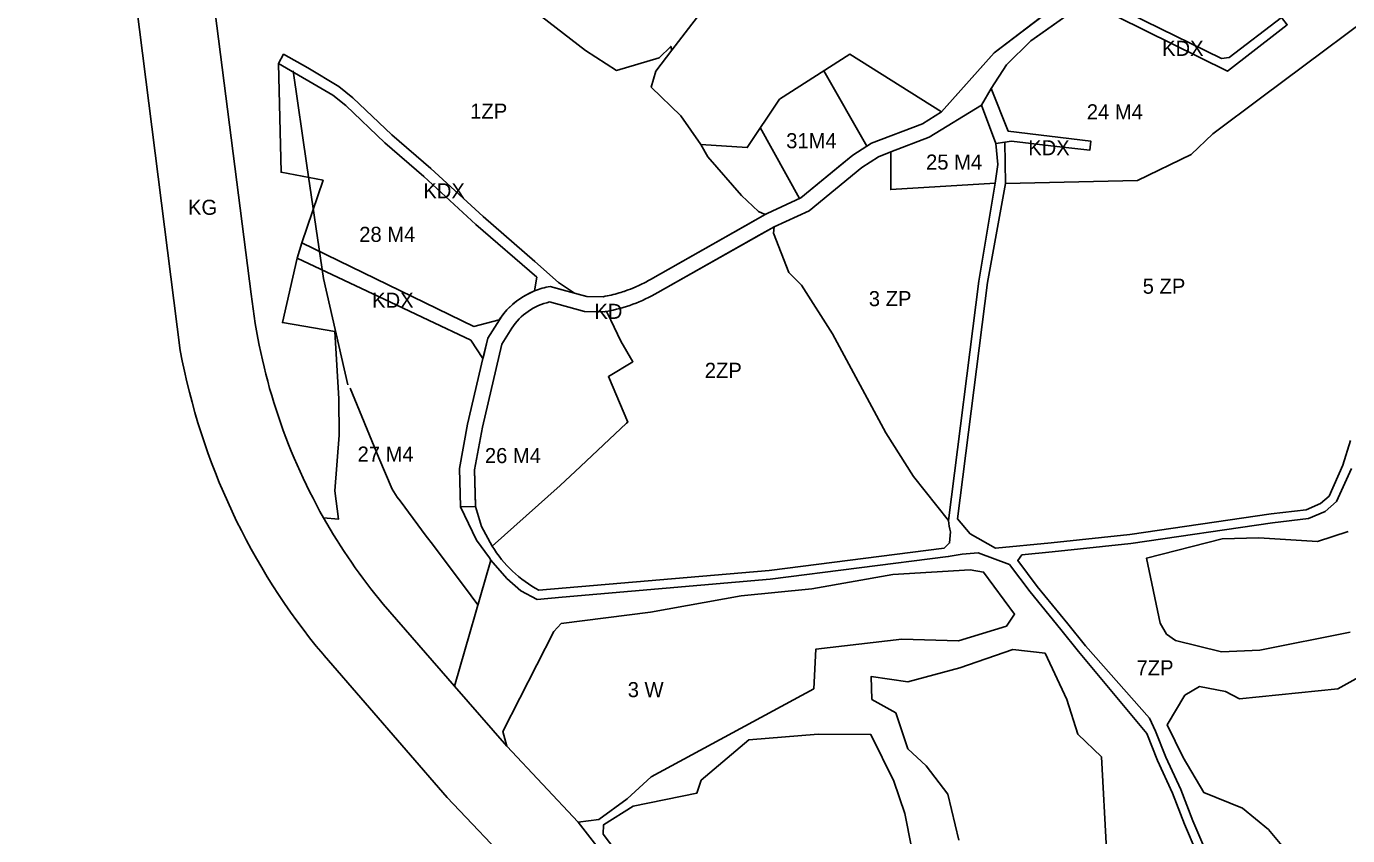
# Model space of a CAD drawing. Extents: x 7437831 to 7440315, y 5545798 to 5547888.
# Drawn here: x 7437831 to 7438706, y 5546452 to 5546989 of the extents above; entities that cross this region are included whole.
import ezdxf

# ---------------------------------------------------------------- set-up
doc = ezdxf.new("R2010")
doc.units = 0
for name, color, linetype in [('linie_rozgraniczajace', 7, 'Continuous'), ('linie_zabudowy_nieprzekraczalne', 7, 'Continuous'), ('oznaczenia_przeznaczen', 7, 'Continuous')]:
    doc.layers.add(name, color=color, linetype=linetype)

msp = doc.modelspace()

# ---------------------------------------------------------------- linework, layer by layer
at = {"layer": 'linie_rozgraniczajace'}
for points in [[(7437933.01, 5546774.06), (7437837.44, 5547527.72), (7437831.07, 5547588.73), (7437881.01, 5547594.89)], [(7437914.41, 5547332.12), (7437921.2, 5547271.7), (7437934.23, 5547169.76), (7437938.07, 5547139.68), (7437980.02, 5546811.4)], [(7437934.23, 5547169.76), (7437970.63, 5547155.76), (7437998.58, 5547150.47), (7438047.18, 5547119.28), (7438140.24, 5547033.26), (7438172.32, 5546995.35), (7438201.42, 5546972.84), (7438222.04, 5546959.64), (7438250.31, 5546968.07), (7438257.95, 5546975.63), (7438258.59, 5546973.05), (7438247.98, 5546959.18), (7438244.98, 5546948.69), (7438264.63, 5546929.64), (7438277.83, 5546910.54)], [(7437980.02, 5546811.4), (7437938.07, 5547139.68)], [(7438532.48, 5547017.36), (7438472.13, 5546971.37), (7438437.2, 5546932.13), (7438424.63, 5546924.38), (7438390.93, 5546911.38), (7438378.56, 5546903.46), (7438344.17, 5546875.23), (7438321.8, 5546864.9), (7438320.38, 5546864.1), (7438244.45, 5546821.11)], [(7438286.71, 5547009.83), (7438258.59, 5546973.05), (7438257.95, 5546975.63), (7438250.31, 5546968.07), (7438222.04, 5546959.64), (7438201.42, 5546972.84), (7438172.32, 5546995.35)], [(7438506.72, 5546997.73), (7438472.13, 5546971.37), (7438440.75, 5546936.12), (7438437.2, 5546932.13), (7438376.65, 5546970.35), (7438329.99, 5546940.55), (7438308.56, 5546908.51), (7438277.83, 5546910.54), (7438264.63, 5546929.64), (7438244.98, 5546948.69), (7438247.98, 5546959.18), (7438258.59, 5546973.05), (7438286.71, 5547009.83)], [(7438708.32, 5546714.39), (7438703.18, 5546697.95), (7438694.12, 5546677.49), (7438688.3, 5546672.47), (7438678.86, 5546668.41), (7438655.79, 5546665.78), (7438562.02, 5546651.94), (7438510.02, 5546646.47), (7438473.12, 5546642.87), (7438456.35, 5546652.39), (7438447.78, 5546662.31), (7438467.86, 5546819.17), (7438479.59, 5546884.81), (7438567.13, 5546886.79), (7438602.71, 5546903.9), (7438616.93, 5546917.59), (7438649.6, 5546941.86), (7438745.98, 5547014.32)], [(7438745.98, 5547014.32), (7438649.6, 5546941.86), (7438616.93, 5546917.59), (7438602.71, 5546903.9), (7438567.13, 5546886.79), (7438479.59, 5546884.81), (7438479.2, 5546912.04), (7438483.68, 5546912.73), (7438509.66, 5546909.77), (7438535.64, 5546906.82), (7438536.32, 5546912.78), (7438481.41, 5546919.46), (7438470.18, 5546947.72), (7438480.26, 5546963.41), (7438496.53, 5546979.31), (7438503.12, 5546983.98), (7438533.91, 5547005.79)], [(7438249.29, 5546812.36), (7438326.34, 5546855.98), (7438349.53, 5546866.69), (7438384.43, 5546895.34), (7438395.47, 5546902.41), (7438403.81, 5546905.63), (7438429.1, 5546915.38), (7438463.79, 5546936.58), (7438470.18, 5546947.72), (7438480.26, 5546963.41), (7438496.53, 5546979.31), (7438533.91, 5547005.79)], [(7438553.99, 5546995.28), (7438626.79, 5546959.29), (7438660.22, 5546985.37), (7438666.3, 5546989.94)], [(7438047.35, 5546941.58), (7438038.13, 5546949.12), (7438017.52, 5546961.31), (7438001.48, 5546970.41), (7437998.03, 5546964.32), (7437999.75, 5546892.18), (7438027.59, 5546886.86), (7438013.46, 5546845.37), (7438010.33, 5546835.23), (7438000.71, 5546792.49), (7438035.35, 5546786.7), (7438038.14, 5546742.05), (7438038.32, 5546717.88), (7438035.28, 5546680.93), (7438037.72, 5546662.16), (7438027.95, 5546663.08)], [(7437998.03, 5546964.32), (7438001.48, 5546970.41)], [(7438169.19, 5546822.55), (7438128.89, 5546857.57), (7438094.38, 5546889.38), (7438068.5, 5546911.77), (7438042.71, 5546936.33), (7438034.11, 5546943.36), (7437998.03, 5546964.32)], [(7437998.03, 5546964.32), (7438034.11, 5546943.36), (7438042.71, 5546936.33), (7438068.5, 5546911.77), (7438094.38, 5546889.38), (7438128.89, 5546857.57), (7438169.19, 5546822.55), (7438167.69, 5546813.52)], [(7438013.46, 5546845.37), (7438027.59, 5546886.86), (7437999.75, 5546892.18), (7437998.03, 5546964.32)], [(7438001.48, 5546970.41), (7438017.52, 5546961.31), (7438038.13, 5546949.12)], [(7438038.13, 5546949.12), (7438047.35, 5546941.58)], [(7438183.6, 5546819.09), (7438167.92, 5546833.05), (7438133.55, 5546862.79), (7438099.05, 5546894.6), (7438073.21, 5546916.96), (7438047.35, 5546941.58)], [(7438047.35, 5546941.58), (7438073.21, 5546916.96), (7438099.05, 5546894.6), (7438133.55, 5546862.79)], [(7438277.83, 5546910.54), (7438282.48, 5546902.5)], [(7438441.97, 5546661.31), (7438461.92, 5546819.96), (7438472.86, 5546884.96), (7438474.55, 5546897.27), (7438473.26, 5546911.13), (7438479.2, 5546912.04), (7438479.59, 5546884.81), (7438467.86, 5546819.17), (7438447.78, 5546662.31), (7438456.35, 5546652.39), (7438473.12, 5546642.87), (7438510.02, 5546646.47), (7438562.02, 5546651.94), (7438655.79, 5546665.78), (7438678.86, 5546668.41), (7438688.3, 5546672.47), (7438694.12, 5546677.49), (7438703.18, 5546697.95), (7438708.32, 5546714.39)], [(7438282.48, 5546902.5), (7438304.81, 5546876.79), (7438316.04, 5546866.24), (7438320.38, 5546864.1), (7438306.02, 5546855.97), (7438244.45, 5546821.11)], [(7438133.55, 5546862.79), (7438167.92, 5546833.05), (7438183.6, 5546819.09)], [(7438249.29, 5546812.36), (7438316.41, 5546850.36), (7438326.34, 5546855.98)], [(7438326.34, 5546855.98), (7438325.91, 5546851.84), (7438336.07, 5546825.77), (7438344.46, 5546817.37), (7438365.13, 5546784.96), (7438400.35, 5546719.38), (7438418.76, 5546690.4), (7438441.97, 5546661.31)], [(7438072.3, 5546806), (7438010.33, 5546835.23), (7438013.46, 5546845.37)], [(7438127.41, 5546789.99), (7438013.46, 5546845.37)], [(7438013.46, 5546845.37), (7438127.41, 5546789.99), (7438144.19, 5546794.23)], [(7438000.71, 5546792.49), (7438010.33, 5546835.23)], [(7438010.33, 5546835.23), (7438072.3, 5546806)], [(7438167.69, 5546813.52), (7438169.19, 5546822.55)], [(7438183.6, 5546819.09), (7438194.07, 5546812.03), (7438186.09, 5546814.24), (7438178.1, 5546816.44)], [(7438213.2, 5546809.68), (7438202.25, 5546809.77), (7438194.07, 5546812.03), (7438178.1, 5546816.44)], [(7438213.2, 5546809.68), (7438202.25, 5546809.77), (7438198.16, 5546810.9), (7438194.07, 5546812.03), (7438183.6, 5546819.09)], [(7438237.26, 5546817.34), (7438234.37, 5546816.04)], [(7438237.26, 5546817.34), (7438234.37, 5546816.04)], [(7438146.01, 5546796.85), (7438136.7, 5546782.23), (7438135.11, 5546775.45), (7438133.8, 5546769.89), (7438133.66, 5546769.28), (7438133.51, 5546768.67), (7438125.44, 5546780.93), (7438097.38, 5546794.17), (7438072.3, 5546806)], [(7438072.3, 5546806), (7438097.38, 5546794.17), (7438125.44, 5546780.93), (7438133.51, 5546768.67)], [(7438177.7, 5546806.18), (7438200.86, 5546799.79), (7438214.02, 5546799.68)], [(7438177.7, 5546806.18), (7438200.86, 5546799.79), (7438214.02, 5546799.68)], [(7438146.01, 5546796.85), (7438136.7, 5546782.23), (7438133.51, 5546768.67), (7438123.3, 5546725.2), (7438117.95, 5546695.7), (7438118.64, 5546670.37), (7438128.63, 5546670.64), (7438128.61, 5546671.49), (7438127.98, 5546694.93), (7438133.1, 5546723.2), (7438146.01, 5546778.23), (7438152.57, 5546788.78), (7438152.57, 5546788.78)], [(7438139.61, 5546644.34), (7438139.58, 5546644.39), (7438184.61, 5546684.53), (7438198.24, 5546696.99), (7438228.5, 5546725.76), (7438229.44, 5546726.45), (7438229.38, 5546726.6), (7438216.62, 5546756.68), (7438232.87, 5546766.57), (7438224.76, 5546780.14), (7438218.22, 5546794.18), (7438215.34, 5546799.91)], [(7438215.34, 5546799.91), (7438218.22, 5546794.18), (7438224.76, 5546780.14), (7438232.87, 5546766.57), (7438216.62, 5546756.68), (7438229.38, 5546726.6)], [(7438038.14, 5546742.05), (7438035.35, 5546786.7), (7438000.71, 5546792.49)], [(7438144.19, 5546794.23), (7438127.41, 5546789.99)], [(7438139.58, 5546644.39), (7438132.49, 5546657.24), (7438128.63, 5546670.64), (7438127.98, 5546694.93), (7438133.1, 5546723.2), (7438146.01, 5546778.23), (7438152.57, 5546788.78)], [(7438133.51, 5546768.67), (7438123.3, 5546725.2), (7438117.95, 5546695.7), (7438118.64, 5546670.37), (7438129.17, 5546648.35)], [(7438027.95, 5546663.08), (7438037.72, 5546662.16), (7438035.28, 5546680.93), (7438038.32, 5546717.88), (7438038.14, 5546742.05)], [(7438229.38, 5546726.6), (7438228.5, 5546725.76)], [(7438228.5, 5546725.76), (7438198.24, 5546696.99), (7438184.61, 5546684.53), (7438139.58, 5546644.39)], [(7438795.44, 5546418.73), (7438685.57, 5546390.27), (7438643.52, 5546380.52), (7438639.21, 5546381.67), (7438634.01, 5546392.39), (7438626.97, 5546407.98), (7438603.87, 5546462.25), (7438595.94, 5546482.98), (7438585.8, 5546504.48), (7438579.13, 5546521.56), (7438575.01, 5546530.35), (7438532.66, 5546578.21), (7438521, 5546592.78), (7438500.73, 5546617.61), (7438487.78, 5546634.71), (7438490.58, 5546638.54), (7438510.63, 5546640.5), (7438562.77, 5546645.99), (7438656.58, 5546659.83), (7438680.41, 5546662.55), (7438691.52, 5546667.32), (7438699.06, 5546673.83), (7438708.8, 5546695.84)], [(7438708.8, 5546695.84), (7438699.06, 5546673.83), (7438691.52, 5546667.32), (7438680.41, 5546662.55), (7438656.58, 5546659.83), (7438562.77, 5546645.99), (7438510.63, 5546640.5), (7438490.58, 5546638.54), (7438487.78, 5546634.71), (7438500.73, 5546617.61), (7438521, 5546592.78), (7438532.66, 5546578.21), (7438575.01, 5546530.35), (7438579.13, 5546521.56), (7438585.8, 5546504.48), (7438595.94, 5546482.98), (7438603.87, 5546462.25), (7438626.97, 5546407.98), (7438634.01, 5546392.39), (7438639.21, 5546381.67), (7438643.52, 5546380.52), (7438685.57, 5546390.27), (7438795.44, 5546418.73)], [(7438461.5, 5546639.77), (7438451.03, 5546639.03), (7438441.79, 5546637.34), (7438323.81, 5546622.3), (7438186, 5546610.39), (7438169.32, 5546608.89), (7438158.64, 5546614.65), (7438149.36, 5546622.88), (7438138.83, 5546635.01), (7438137.82, 5546636.54), (7438129.17, 5546648.35), (7438118.64, 5546670.37), (7438128.63, 5546670.64)], [(7438128.63, 5546670.64), (7438132.49, 5546657.24), (7438139.58, 5546644.39), (7438139.61, 5546644.34)], [(7438129.17, 5546648.35), (7438137.82, 5546636.54), (7438138.83, 5546635.01)], [(7438443.15, 5546653.73), (7438442.68, 5546646.45), (7438439.11, 5546643.06), (7438323.13, 5546628.26), (7438170.5, 5546615.07)], [(7438170.5, 5546615.07), (7438323.13, 5546628.26), (7438439.11, 5546643.06), (7438442.68, 5546646.45), (7438443.15, 5546653.73)], [(7438706.64, 5546654.04), (7438686.36, 5546647.35), (7438647.59, 5546649.72), (7438623.25, 5546649.06), (7438573.17, 5546636.38), (7438582.14, 5546593.25), (7438586.26, 5546586.04), (7438592.23, 5546581.74), (7438622.86, 5546574.24), (7438648.07, 5546575.31), (7438708.08, 5546587.26)], [(7438708.08, 5546587.26), (7438648.07, 5546575.31), (7438622.86, 5546574.24), (7438592.23, 5546581.74), (7438586.26, 5546586.04), (7438582.14, 5546593.25), (7438573.17, 5546636.38), (7438623.25, 5546649.06), (7438647.59, 5546649.72), (7438686.36, 5546647.35), (7438706.64, 5546654.04)], [(7438298.35, 5546330.31), (7438196.67, 5546461.27), (7438210.21, 5546463.09), (7438229.14, 5546476.84), (7438244.85, 5546491.45), (7438352.63, 5546549.79), (7438354.1, 5546576.08), (7438410.94, 5546582.55), (7438448.57, 5546581.57), (7438480.31, 5546591.18), (7438485.66, 5546599.29), (7438465.2, 5546627.15), (7438456.27, 5546628.56), (7438405.07, 5546625.48), (7438351.29, 5546616.07), (7438304.67, 5546611.34), (7438244.46, 5546600.49), (7438185.43, 5546593.04), (7438180.38, 5546587.79), (7438146.59, 5546521.34), (7438149.26, 5546511.75), (7438114.61, 5546551.54), (7438138.83, 5546635.01), (7438149.36, 5546622.88), (7438158.64, 5546614.65), (7438169.32, 5546608.89), (7438186, 5546610.39), (7438323.81, 5546622.3), (7438441.79, 5546637.34), (7438451.03, 5546639.03), (7438461.5, 5546639.77), (7438482.25, 5546632.08), (7438496.01, 5546613.9), (7438516.33, 5546589.01), (7438528.01, 5546574.42), (7438573.27, 5546520.07), (7438580.28, 5546502.11), (7438590.41, 5546480.63), (7438598.3, 5546460), (7438621.47, 5546405.58)], [(7438138.83, 5546635.01), (7438114.61, 5546551.54)], [(7438707.78, 5546325.74), (7438705.04, 5546335.85), (7438689.64, 5546345.13), (7438659.33, 5546361.84), (7438635.81, 5546374.92), (7438628.58, 5546389.85), (7438621.47, 5546405.58), (7438598.3, 5546460), (7438590.41, 5546480.63), (7438580.28, 5546502.11), (7438573.27, 5546520.07), (7438528.01, 5546574.42), (7438516.33, 5546589.01), (7438496.01, 5546613.9), (7438482.25, 5546632.08)], [(7438067.49, 5546605.86), (7438114.61, 5546551.54), (7438149.26, 5546511.75), (7438196.67, 5546461.27)], [(7438114.61, 5546551.54), (7438067.49, 5546605.86)], [(7438196.67, 5546461.27), (7438298.35, 5546330.31), (7438327.02, 5546299.69), (7438441.63, 5546163.98), (7438457.31, 5546145.41), (7438417.85, 5546111.55), (7438288.22, 5546265.05), (7438258.75, 5546296.53), (7438155.6, 5546429.38), (7438109.87, 5546477.65), (7438028.21, 5546571.79), (7438027.55, 5546572.58)], [(7438546.51, 5546443.09), (7438543.27, 5546504.72), (7438527.51, 5546519.56), (7438520.33, 5546542.54), (7438505.94, 5546573.38), (7438484.57, 5546575.67), (7438449.41, 5546563.66), (7438415, 5546554.38), (7438390.74, 5546557.97), (7438391.13, 5546542.7), (7438406.99, 5546533.78), (7438415.08, 5546510.03), (7438427.21, 5546498.59), (7438441.42, 5546479.8), (7438448.79, 5546449.27)], [(7438448.79, 5546449.27), (7438441.42, 5546479.8), (7438427.21, 5546498.59), (7438415.08, 5546510.03), (7438406.99, 5546533.78), (7438391.13, 5546542.7), (7438390.74, 5546557.97), (7438415, 5546554.38), (7438449.41, 5546563.66), (7438484.57, 5546575.67), (7438505.94, 5546573.38), (7438520.33, 5546542.54), (7438527.51, 5546519.56), (7438543.27, 5546504.72), (7438546.51, 5546443.09)], [(7438735.57, 5546569.53), (7438699.95, 5546549.81), (7438634.72, 5546543.09), (7438625.39, 5546547.96), (7438608.24, 5546551.18), (7438598.55, 5546545.46), (7438586.82, 5546525.85), (7438597.33, 5546504.17), (7438611.07, 5546480.91), (7438636.69, 5546470.6), (7438654.01, 5546456.4), (7438662.73, 5546445.9), (7438655.6, 5546436.86), (7438647.14, 5546430.84), (7438644.08, 5546425.54), (7438646.83, 5546414.2), (7438656.25, 5546403.03), (7438665.92, 5546401.94), (7438680.49, 5546422.88), (7438699.67, 5546442.72), (7438716.97, 5546447.82)], [(7438716.97, 5546447.82), (7438699.67, 5546442.72), (7438680.49, 5546422.88), (7438665.92, 5546401.94), (7438656.25, 5546403.03), (7438646.83, 5546414.2), (7438644.08, 5546425.54), (7438647.14, 5546430.84), (7438655.6, 5546436.86), (7438662.73, 5546445.9), (7438654.01, 5546456.4), (7438636.69, 5546470.6), (7438611.07, 5546480.91), (7438597.33, 5546504.17), (7438586.82, 5546525.85), (7438598.55, 5546545.46), (7438608.24, 5546551.18), (7438625.39, 5546547.96), (7438634.72, 5546543.09), (7438699.95, 5546549.81), (7438735.57, 5546569.53)], [(7438426.51, 5546399.09), (7438413.02, 5546467.01), (7438405.69, 5546488.56), (7438390.5, 5546519.36), (7438355.54, 5546519.71), (7438309.62, 5546515.8), (7438278.06, 5546489.08), (7438275.18, 5546480.5), (7438233.01, 5546471.91), (7438213.41, 5546459.62), (7438213.04, 5546453.35), (7438296.89, 5546343)], [(7438296.89, 5546343), (7438213.04, 5546453.35), (7438213.41, 5546459.62), (7438233.01, 5546471.91), (7438275.18, 5546480.5), (7438278.06, 5546489.08), (7438309.62, 5546515.8), (7438355.54, 5546519.71), (7438390.5, 5546519.36), (7438405.69, 5546488.56), (7438413.02, 5546467.01), (7438426.51, 5546399.09)]]:
    msp.add_lwpolyline(points, dxfattribs=at)
for points in [[(7438647.86, 5547095.7), (7438683.78, 5547047.94), (7438702.01, 5547023.71), (7438696.78, 5547021.72), (7438676.76, 5547010.19), (7438670.05, 5547000.07), (7438662.56, 5546994.72), (7438627.88, 5546968.17), (7438622.69, 5546967.65), (7438561.76, 5546997.32), (7438541.56, 5547009.95), (7438541.58, 5547011.8), (7438547.65, 5547016.72), (7438586.53, 5547048.24), (7438638.89, 5547088.76)], [(7438541.58, 5547011.8), (7438541.56, 5547009.95), (7438561.76, 5546997.32), (7438622.69, 5546967.65), (7438627.88, 5546968.17), (7438662.56, 5546994.72), (7438666.3, 5546989.94), (7438660.22, 5546985.37), (7438626.79, 5546959.29), (7438553.99, 5546995.28), (7438536.47, 5547005.96), (7438533.91, 5547005.79)], [(7438277.83, 5546910.54), (7438308.56, 5546908.51), (7438329.99, 5546940.55), (7438376.65, 5546970.35), (7438437.2, 5546932.13), (7438424.63, 5546924.38), (7438390.93, 5546911.38), (7438378.56, 5546903.46), (7438371.48, 5546897.65), (7438344.17, 5546875.23), (7438321.8, 5546864.9), (7438321.09, 5546864.5), (7438320.38, 5546864.1), (7438316.04, 5546866.24), (7438304.81, 5546876.79), (7438282.48, 5546902.5)], [(7438470.18, 5546947.72), (7438481.41, 5546919.46), (7438536.32, 5546912.78), (7438535.64, 5546906.82), (7438509.66, 5546909.77), (7438483.68, 5546912.73), (7438479.2, 5546912.04), (7438473.26, 5546911.13), (7438463.79, 5546936.58)], [(7438463.79, 5546936.58), (7438473.26, 5546911.13), (7438474.55, 5546897.27), (7438472.86, 5546884.96), (7438403.69, 5546880.67), (7438403.81, 5546905.63), (7438429.1, 5546915.38)], [(7438403.81, 5546905.63), (7438403.69, 5546880.67), (7438472.86, 5546884.96), (7438461.92, 5546819.96), (7438441.97, 5546661.31), (7438418.76, 5546690.4), (7438400.35, 5546719.38), (7438365.13, 5546784.96), (7438344.46, 5546817.37), (7438336.07, 5546825.77), (7438325.91, 5546851.84), (7438326.34, 5546855.98), (7438349.53, 5546866.69), (7438384.43, 5546895.34), (7438389.95, 5546898.88), (7438395.47, 5546902.41)], [(7438149.26, 5546511.75), (7438146.59, 5546521.34), (7438180.38, 5546587.79), (7438185.43, 5546593.04), (7438244.46, 5546600.49), (7438304.67, 5546611.34), (7438351.29, 5546616.07), (7438405.07, 5546625.48), (7438456.27, 5546628.56), (7438465.2, 5546627.15), (7438485.66, 5546599.29), (7438480.31, 5546591.18), (7438448.57, 5546581.57), (7438410.94, 5546582.55), (7438354.1, 5546576.08), (7438352.63, 5546549.79), (7438244.85, 5546491.45), (7438229.14, 5546476.84), (7438210.21, 5546463.09), (7438196.67, 5546461.27)]]:
    msp.add_lwpolyline(points, close=True, dxfattribs=at)
for centre, radius, start, end in [((7438186.4708, 5546766.5814), 50.5564, 99.530536, 111.8070293), ((7438186.3447, 5546767.0308), 50.0924, 99.4734465, 111.8641189), ((7438195.305, 5546906.9404), 98.9392, 289.3148523, 293.25592), ((7438195.305, 5546906.9404), 98.9392, 289.3148523, 293.25592), ((7438197.0615, 5546902.7462), 94.3936, 295.2051341, 300.134449), ((7438197.0615, 5546902.7462), 94.3936, 295.2051341, 300.134449), ((7438365.2324, 5546853.9781), 387.5584, 186.3073785, 209.5093731), ((7438365.2324, 5546853.9781), 387.5584, 186.3073785, 209.5093731), ((7438186.3595, 5546766.8068), 50.3058, 111.7846731, 143.3295181), ((7438186.3306, 5546766.8537), 50.2516, 111.7740023, 140.9236684), ((7438186.3878, 5546766.7856), 40.341, 102.4365488, 146.9608714), ((7438186.3878, 5546766.7856), 40.341, 102.4365488, 146.9608714), ((7438195.9652, 5546905.6292), 97.4848, 280.1831363, 286.5230819), ((7438197.844, 5546896.611), 88.2769, 280.0177442, 283.5188337), ((7438196.501, 5546903.7964), 105.5807, 280.2784361, 299.9991295), ((7438196.501, 5546903.7964), 105.5807, 280.2784361, 299.9991295), ((7438200.163, 5546889.8948), 81.2075, 283.0356723, 286.8408511), ((7438195.918, 5546904.9962), 96.8983, 286.6489319, 289.3474503), ((7438200.6275, 5546891.0908), 82.2215, 286.2896062, 289.467787), ((7438182.6209, 5546769.4759), 45.7132, 143.2143664, 147.2135796), ((7438182.6209, 5546769.4759), 45.7132, 143.2143664, 147.2135796), ((7438190.9897, 5546763.1273), 56.2173, 140.9685648, 143.1399387), ((7438206.86, 5546844.675), 45.5611, 279.0415997, 280.7266483), ((7438206.86, 5546844.675), 45.5611, 279.0415997, 280.7266483), ((7438365.3475, 5546854.0044), 439.6667, 190.4763381, 219.798204), ((7438364.4983, 5546853.3693), 386.6197, 209.4844406, 219.8058339), ((7438364.4983, 5546853.3693), 386.6197, 209.4844406, 219.8058339), ((7438480.2525, 5546663.3877), 38.3388, 183.1065491, 194.5902001), ((7438480.2525, 5546663.3877), 38.3388, 183.1065491, 194.5902001), ((7438209.6738, 5546687.3468), 82.2102, 211.5425609, 241.542437), ((7438209.6738, 5546687.3468), 82.2102, 211.5425609, 241.542437)]:
    msp.add_arc(centre, radius, start, end, dxfattribs=at)
at = {"layer": 'linie_zabudowy_nieprzekraczalne'}
for points in [[(7438007.74, 5546959.3), (7438016.91, 5546896.59), (7438027.88, 5546821.74), (7438044.09, 5546751.32)], [(7438359.42, 5546959.34), (7438387.87, 5546909.42)], [(7438317.1, 5546921.89), (7438343.19, 5546874.78)], [(7438045.51, 5546748.96), (7438064.55, 5546702.93), (7438073.26, 5546682.14), (7438076.65, 5546676.69), (7438078.71, 5546674.31), (7438095.95, 5546650.91), (7438100.13, 5546645.53), (7438112.37, 5546628.98), (7438121.2, 5546617.38), (7438130.19, 5546605.38)]]:
    msp.add_lwpolyline(points, dxfattribs=at)

# ---------------------------------------------------------------- texts
at = {"layer": 'oznaczenia_przeznaczen'}
for s, p in [('KDX', (7438583.4043, 5546969.31)), ('1ZP', (7438125.0852, 5546927.72)), ('24 M4', (7438533.5405, 5546927.24)), ('31M4', (7438334.4028, 5546908.09)), ('31M4', (7438334.4028, 5546908.09)), ('KDX', (7438494.7243, 5546903.43)), ('25 M4', (7438427.0505, 5546893.93)), ('KDX', (7438094.0343, 5546874.87)), ('KG', (7437938.0927, 5546863.95)), ('28 M4', (7438051.5605, 5546846.01)), ('5 ZP', (7438570.5629, 5546811.64)), ('KDX', (7438060.0943, 5546802.34)), ('3 ZP', (7438389.1229, 5546803.4)), ('KD', (7438207.3227, 5546794.97)), ('2ZP', (7438280.4752, 5546755.87)), ('27 M4', (7438050.4505, 5546700.31)), ('26 M4', (7438134.7905, 5546699.34)), ('7ZP', (7438566.4952, 5546558.66)), ('3 W', (7438229.4043, 5546544.17))]:
    msp.add_text(s, height=10, dxfattribs=at).set_placement(p)

doc.saveas('drawing.dxf')
